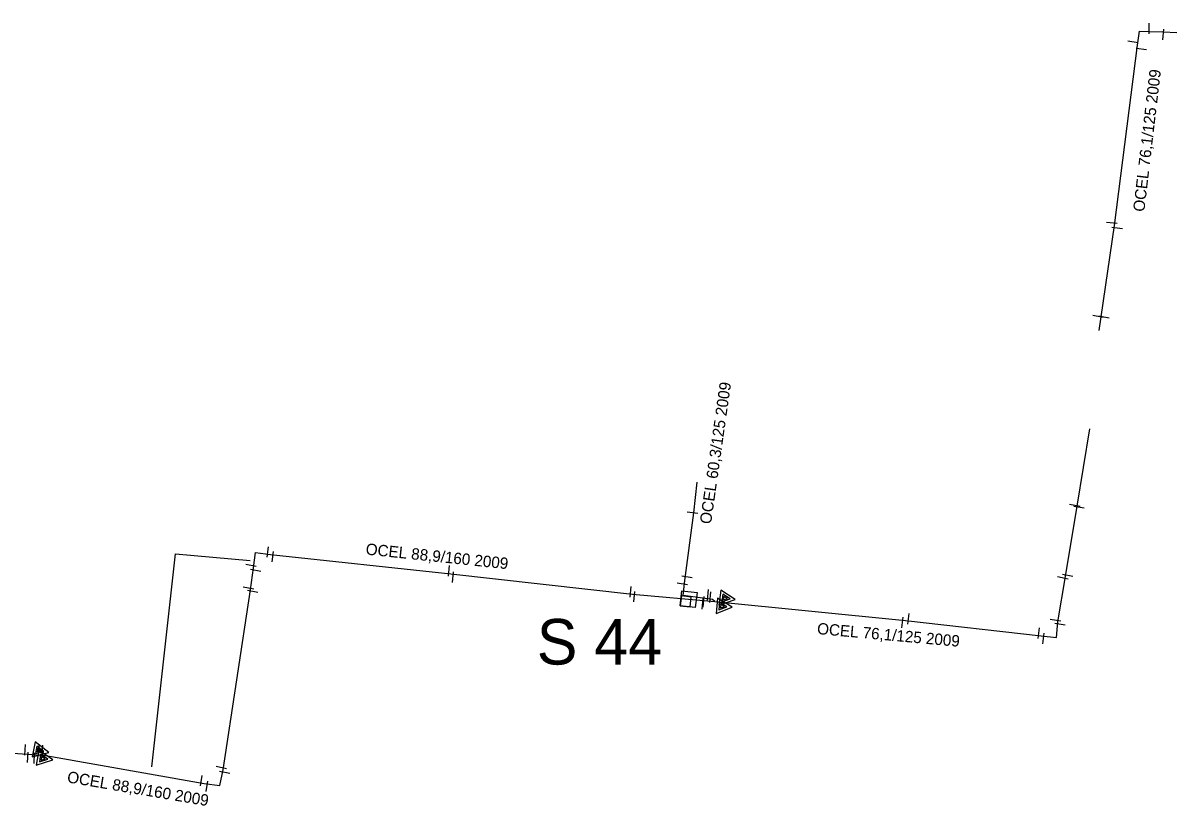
# Model space of a CAD drawing. Extents: x -642943 to -623314, y -1138561 to -1113539.
# Drawn here: x -642350.2 to -642274.2, y -1114256.6 to -1114205.1 of the extents above; entities that cross this region are included whole.
import ezdxf

# ---------------------------------------------------------------- set-up
doc = ezdxf.new("R2010")
doc.units = 0
for name, color, linetype in [('horkovod armatury', 7, 'Continuous'), ('horkovod dimenze', 7, 'Continuous'), ('horkovod předisol', 7, 'Continuous'), ('horkovod sváry', 7, 'Continuous'), ('horkovod trasa', 7, 'Continuous'), ('horkovod zrušený', 7, 'Continuous'), ('horkovod číslo šachty', 7, 'Continuous'), ('horkovod šachty', 7, 'Continuous')]:
    doc.layers.add(name, color=color, linetype=linetype)

# ---------------------------------------------------------------- blocks, each defined once
blk = doc.blocks.new('SPH')
at = {"layer": 'horkovod sváry'}
blk.add_line((0, -0.035), (0, 0.035), dxfattribs=at)
blk = doc.blocks.new('SPH_1')
at = {"layer": 'horkovod sváry'}
blk.add_line((0.0001, -0.035), (-0.0001, 0.035), dxfattribs=at)
blk = doc.blocks.new('POINT_DISPLAY')
blk.add_line((0, 0), (0, 0))
blk = doc.blocks.new('PREDU_1')
at = {"layer": 'horkovod armatury'}
for p, q in [((-0.0007, 0.0677), (-0.0502, -0.0344)), ((-0.0003, 0.0342), (-0.0249, -0.0171)), ((-0.0002, 0.0177), (-0.0119, -0.0084)), ((0.0509, -0.0333), (-0.0007, 0.0677)), ((0.0251, -0.0166), (-0.0003, 0.0342)), ((0.0121, -0.0082), (-0.0002, 0.0177)), ((-0.0502, -0.0344), (0.0509, -0.0333)), ((-0.0249, -0.0171), (0.0251, -0.0166)), ((-0.0119, -0.0084), (0.0121, -0.0082))]:
    blk.add_line(p, q, dxfattribs=at)

msp = doc.modelspace()

# ---------------------------------------------------------------- linework, layer by layer
at = {"layer": 'horkovod předisol'}
for points in [[(-642279.367, -1114225.318), (-642279.235, -1114224.407), (-642278.348, -1114218.4), (-642276.849, -1114206.534), (-642276.704, -1114205.602), (-642276.076, -1114205.619), (-642275.143, -1114205.652), (-642274.243, -1114205.703)], [(-642304.669, -1114243.154), (-642292.109, -1114244.418), (-642283.178, -1114245.42), (-642282.173, -1114245.527), (-642282.08, -1114244.506), (-642281.589, -1114241.508), (-642280.823, -1114236.89), (-642279.975, -1114231.799)], [(-642304.669, -1114243.154), (-642304.825, -1114243.034), (-642306.768, -1114242.753), (-642306.652, -1114241.767), (-642306.058, -1114237.328), (-642305.826, -1114235.31)], [(-642348.729, -1114253.299), (-642338.308, -1114255.139), (-642337.272, -1114255.264), (-642337.053, -1114254.234), (-642335.242, -1114242.389), (-642335.055, -1114240.935), (-642334.925, -1114239.938), (-642333.93, -1114240.054), (-642322.053, -1114241.337), (-642310.105, -1114242.669), (-642304.669, -1114243.154)], [(-642364.358, -1114255.556), (-642364.095, -1114252.199), (-642348.729, -1114253.299)]]:
    msp.add_lwpolyline(points, dxfattribs=at)
at = {"layer": 'horkovod trasa'}
for points in [[(-642279.367, -1114225.318), (-642279.235, -1114224.407), (-642278.348, -1114218.4), (-642276.849, -1114206.534), (-642276.704, -1114205.602), (-642276.076, -1114205.619), (-642275.143, -1114205.652), (-642274.243, -1114205.703)], [(-642304.669, -1114243.154), (-642292.109, -1114244.418), (-642283.178, -1114245.42), (-642282.173, -1114245.527), (-642282.08, -1114244.506), (-642281.589, -1114241.508), (-642280.823, -1114236.89), (-642279.975, -1114231.799)], [(-642304.669, -1114243.154), (-642304.825, -1114243.034), (-642306.768, -1114242.753), (-642306.652, -1114241.767), (-642306.058, -1114237.328), (-642305.826, -1114235.31)], [(-642348.729, -1114253.299), (-642338.308, -1114255.139), (-642337.272, -1114255.264), (-642337.053, -1114254.234), (-642335.242, -1114242.389), (-642335.055, -1114240.935), (-642334.925, -1114239.938), (-642333.93, -1114240.054), (-642322.053, -1114241.337), (-642310.105, -1114242.669), (-642304.669, -1114243.154)], [(-642364.358, -1114255.556), (-642364.095, -1114252.199), (-642348.729, -1114253.299)]]:
    msp.add_lwpolyline(points, dxfattribs=at)
at = {"layer": 'horkovod zrušený'}
msp.add_lwpolyline([(-642341.741, -1114254.043), (-642340.179, -1114240.02), (-642335.276, -1114240.465)], dxfattribs=at)
at = {"layer": 'horkovod šachty'}
for p, q in [((-642306.875, -1114242.795), (-642306.949, -1114243.44)), ((-642306.23, -1114242.869), (-642306.875, -1114242.795)), ((-642306.304, -1114243.514), (-642306.23, -1114242.869)), ((-642306.949, -1114243.44), (-642306.304, -1114243.514))]:
    msp.add_line(p, q, dxfattribs=at)
msp.add_lwpolyline([(-642306.954, -1114243.44), (-642306.84, -1114242.447), (-642305.846, -1114242.561), (-642305.961, -1114243.555), (-642306.954, -1114243.44)], dxfattribs=at)

# ---------------------------------------------------------------- block references
at = {"layer": 'horkovod armatury'}
for p, xscale, yscale, rotation in [((-642304.012, -1114242.95), 9.999996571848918, 9.999996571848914, -97.53411627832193), ((-642304.212, -1114243.47), 10.000022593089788, 10.000022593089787, -95.42100630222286), ((-642349.192, -1114252.96), 9.999991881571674, 9.999991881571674, -101.6920629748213), ((-642348.942, -1114253.49), 9.999976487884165, 9.999976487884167, -99.4714456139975)]:
    msp.add_blockref('PREDU_1', p, dxfattribs=dict(at, xscale=xscale, yscale=yscale, rotation=rotation))
at = {"layer": 'horkovod sváry', "xscale": 10, "yscale": 10}
msp.add_blockref('SPH_1', (-642276.079, -1114205.424), dxfattribs=at)
at = {"layer": 'horkovod sváry'}
for name, p, xscale, yscale, rotation in [('SPH_1', (-642275.139, -1114205.827), 9.999998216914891, 9.99999821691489, -3.968692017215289), ('SPH_1', (-642277.134, -1114206.33), 9.999990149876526, 9.999990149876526, 80.81949528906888), ('SPH', (-642276.584, -1114206.79), 10.000015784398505, 10.000015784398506, 83.15352853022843), ('SPH_1', (-642278.534, -1114218.23), 9.999997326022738, 9.999997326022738, 83.95795237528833), ('SPH', (-642278.174, -1114218.58), 10.000003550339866, 10.000003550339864, 82.32645812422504), ('SPH', (-642279.434, -1114224.4), 9.999997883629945, 9.999997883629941, 79.8695500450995), ('SPH', (-642279.044, -1114224.44), 10.000018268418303, 10.000018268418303, 79.68847169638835), ('SPH', (-642280.964, -1114236.83), 10.000007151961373, 10.00000715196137, 78.70246847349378), ('SPH_1', (-642280.694, -1114236.96), 10.00000866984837, 10.00000866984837, 79.76357082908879), ('SPH_1', (-642306.144, -1114237.32), 10.000014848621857, 10.000014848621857, 82.05501032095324), ('SPH_1', (-642334.104, -1114239.9), 10.000008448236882, 10.000008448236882, -6.928443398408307), ('SPH_1', (-642333.784, -1114240.21), 10.000020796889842, 10.000020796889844, -7.440989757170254), ('SPH_1', (-642335.214, -1114240.79), 10.00002111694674, 10.000021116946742, 80.09580427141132), ('SPH_1', (-642322.174, -1114241.14), 9.999994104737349, 9.999994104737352, -4.999059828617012), ('SPH_1', (-642334.914, -1114241.12), 9.999999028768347, 9.999999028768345, 78.98120349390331), ('SPH_1', (-642321.914, -1114241.55), 9.999980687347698, 9.999980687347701, -4.253847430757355), ('SPH_1', (-642306.504, -1114241.54), 9.999995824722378, 9.999995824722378, 81.05644600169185), ('SPH', (-642281.754, -1114241.61), 10.000016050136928, 10.000016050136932, 78.68996287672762), ('SPH_1', (-642281.444, -1114241.44), 10.0000240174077, 10.0000240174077, 78.5841101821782), ('SPH_1', (-642335.384, -1114242.28), 10.00001624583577, 10.000016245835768, 79.28495687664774), ('SPH_1', (-642335.114, -1114242.5), 10.000014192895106, 10.000014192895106, 79.11274976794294), ('SPH', (-642310.224, -1114242.52), 9.999987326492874, 9.999987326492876, -5.3449171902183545), ('SPH_1', (-642309.974, -1114242.84), 9.999994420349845, 9.999994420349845, -5.467119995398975), ('SPH_1', (-642306.814, -1114242.01), 10.000010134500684, 10.000010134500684, 81.75209873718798), ('SPH_1', (-642305.124, -1114242.72), 9.99999322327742, 9.999993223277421, -5.9524468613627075), ('SPH_1', (-642305.474, -1114243.32), 9.99997913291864, 9.999979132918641, -5.629037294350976), ('SPH', (-642305.404, -1114243.18), 9.999979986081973, 9.999979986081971, -5.016475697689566), ('SPH', (-642304.974, -1114242.88), 9.999989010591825, 9.999989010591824, -5.339288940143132), ('SPH_1', (-642291.924, -1114244.3), 9.999982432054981, 9.999982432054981, -6.568447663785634), ('SPH_1', (-642292.314, -1114244.54), 9.999983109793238, 9.999983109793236, -7.2599701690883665), ('SPH_1', (-642282.234, -1114244.39), 10.000001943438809, 10.000001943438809, 80.94704921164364), ('SPH_1', (-642281.944, -1114244.66), 10.000000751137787, 10.00000075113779, 81.95773750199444), ('SPH', (-642283.334, -1114245.25), 9.999976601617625, 9.999976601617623, -6.486007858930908), ('SPH_1', (-642283.034, -1114245.59), 10.000007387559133, 10.000007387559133, -6.5673569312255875), ('SPH', (-642350.089, -1114252.92), 9.999984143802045, 9.999984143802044, -4.1521865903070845), ('SPH', (-642349.909, -1114253.42), 10.00002524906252, 10.000025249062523, -3.5692112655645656), ('SPH', (-642349.479, -1114253.47), 10.000005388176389, 10.00000538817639, -1.274363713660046), ('SPH', (-642349.189, -1114252.96), 10.000004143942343, 10.000004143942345, -3.003995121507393), ('SPH', (-642348.959, -1114252.97), 9.999981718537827, 9.999981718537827, -5.037901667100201), ('SPH_1', (-642338.484, -1114254.95), 9.999991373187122, 9.999991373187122, -10.370137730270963), ('SPH', (-642337.174, -1114254.1), 9.999986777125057, 9.999986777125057, 76.02561905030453), ('SPH_1', (-642336.954, -1114254.42), 9.999969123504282, 9.99996912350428, 77.73268712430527), ('SPH_1', (-642338.114, -1114255.33), 9.999983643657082, 9.99998364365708, -8.591267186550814)]:
    msp.add_blockref(name, p, dxfattribs=dict(at, xscale=xscale, yscale=yscale, rotation=rotation))
at = {"layer": 'horkovod šachty'}
msp.add_blockref('POINT_DISPLAY', (-642306.584, -1114243.15), dxfattribs=at)

# ---------------------------------------------------------------- texts
at = {"layer": 'horkovod dimenze'}
for s, height, rotation, p in [('OCEL 76,1/125 2009', 0.75, 83.29016, (-642276.391, -1114217.526)), ('OCEL 60,3/125 2009', 0.74995, 81.8699, (-642304.926, -1114238.094)), ('OCEL 88,9/160 2009', 0.75, 354.06601, (-642327.69, -1114240.063)), ('OCEL 76,1/125 2009', 0.75, 354.86201, (-642297.961, -1114245.301)), ('OCEL 88,9/160 2009', 0.75, 350.35761, (-642347.363, -1114255.059))]:
    msp.add_text(s, height=height, rotation=rotation, dxfattribs=at).set_placement(p)
at = {"layer": 'horkovod číslo šachty'}
msp.add_text('S 44', height=3, dxfattribs=at).set_placement((-642316.397, -1114247.31))

doc.saveas('drawing.dxf')
